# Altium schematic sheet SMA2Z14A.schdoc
size 127 x 101 mm
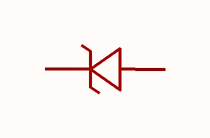
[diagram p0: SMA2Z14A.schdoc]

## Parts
D?  sma2z14a  [SMAG_L4.3-W2.6-LS5.3-RD]  (value not drawn)

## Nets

Not connected (* = marked no-connect by the designer): D? 1(K) 2(A)

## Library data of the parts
D? = sma2z14a: 二极管配置:1个独立式;稳压值(标称值):14V;稳压值(范围值):13.3V~14.7V;耗散功率(Pd):2W;; Manufacturer: CJ(江苏长电/长晶); AddInBom: yes; ModelId: 3cd8680d946b497db8ea5837610a9736; ModelTransform: 208.661,102.362,0,0,0,0,0,0,0; Diode Configuration: 1个独立式; Zener Voltage(Nom): 14V; Reverse Leakage Current (Ir): 500nA@10.6V; Pd - Power Dissipation: 2W; Impedance(Zzt): 5.5Ω; Impedance(Zzk): 700Ω; Operating Junction Temperature Range: -55℃~+150℃; Tolerance: ±5%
